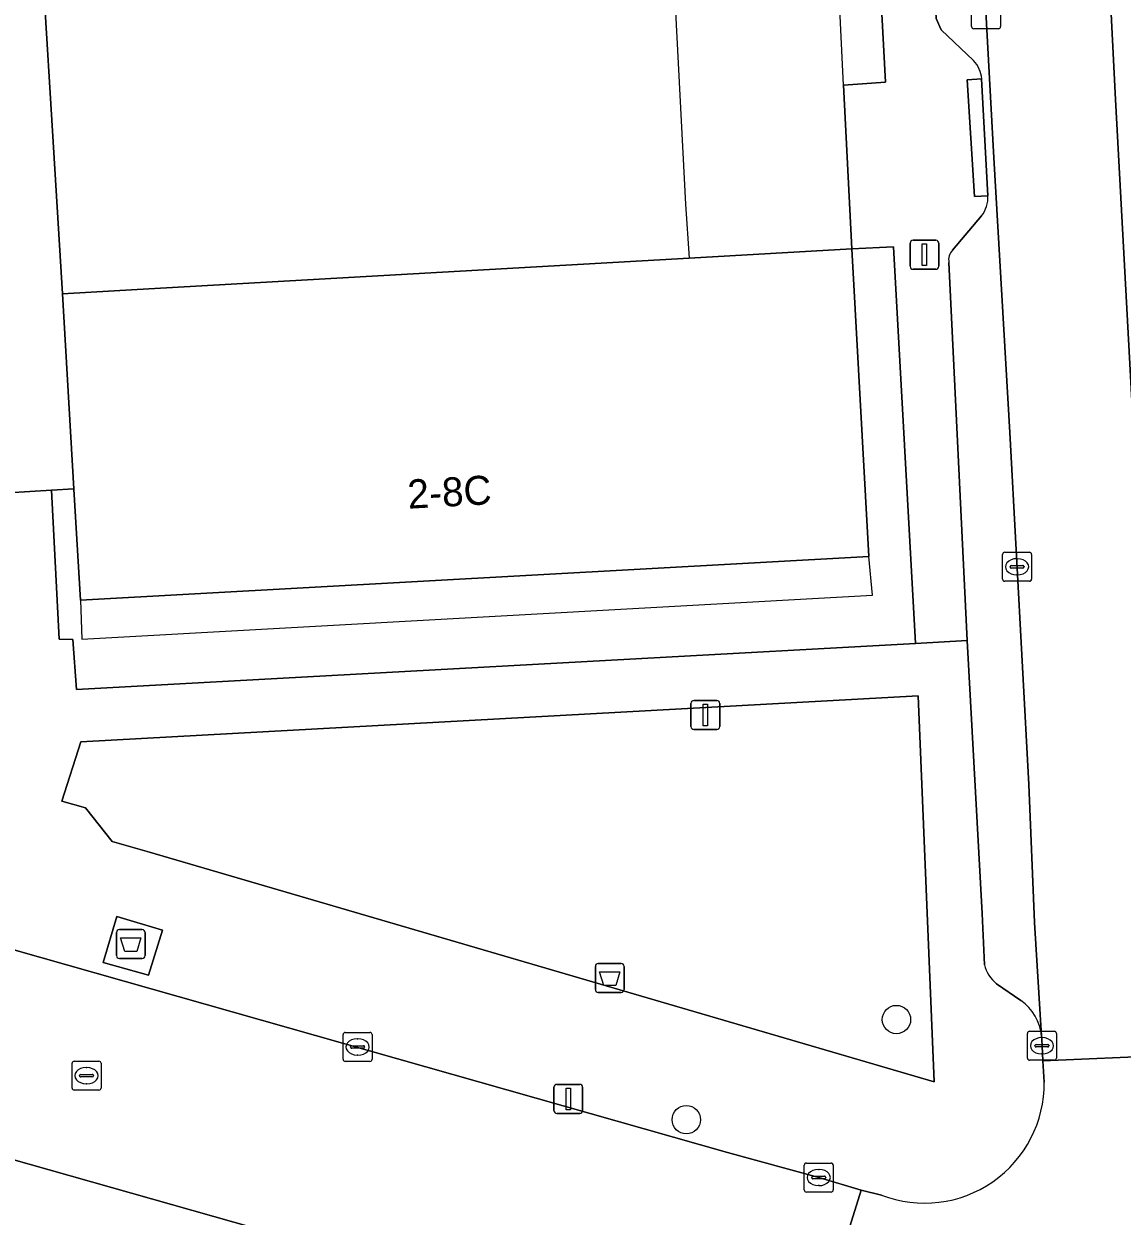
# Model space of a CAD drawing. Extents: x 158086 to 159499, y 382904 to 383981.
# Drawn here: x 158859.59 to 158897.48, y 383363.6 to 383404.74 of the extents above; entities that cross this region are included whole.
import ezdxf

# ---------------------------------------------------------------- set-up
doc = ezdxf.new("R2010")
doc.units = 0
for name, color, linetype in [('IMGEO_Afval_apart_plaats', 7, 'Continuous'), ('IMGEO_Afvalbak', 7, 'Continuous'), ('IMGEO_Boom', 7, 'Continuous'), ('IMGEO_Erf', 7, 'Continuous'), ('IMGEO_Groenvoorziening', 7, 'Continuous'), ('IMGEO_Kolk', 7, 'Continuous'), ('IMGEO_Lichtmast', 7, 'Continuous'), ('IMGEO_Pand', 7, 'Continuous'), ('IMGEO_Pand_nummerreeks', 7, 'Continuous'), ('IMGEO_Pand_overbouw', 7, 'Continuous'), ('IMGEO_Parkeervlak_open', 7, 'Continuous'), ('IMGEO_Rijbaan_lokaal_open', 7, 'Continuous'), ('IMGEO_Rioolput', 7, 'Continuous'), ('IMGEO_Voetpad_gesloten', 7, 'Continuous'), ('IMGEO_Voetpad_open', 7, 'Continuous')]:
    doc.layers.add(name, color=color, linetype=linetype)

msp = doc.modelspace()

# ---------------------------------------------------------------- linework, layer by layer
at = {"layer": 'IMGEO_Afval_apart_plaats'}
for p, q in [((158862.787, 383372.589), (158862.787, 383373.389)), ((158862.787, 383373.389), (158862.787, 383372.589)), ((158862.887, 383373.489), (158863.677, 383373.489)), ((158863.677, 383373.489), (158862.887, 383373.489)), ((158863.777, 383373.389), (158863.777, 383372.589)), ((158863.777, 383372.589), (158863.777, 383373.389)), ((158863.677, 383372.489), (158862.887, 383372.489)), ((158862.887, 383372.489), (158863.677, 383372.489))]:
    msp.add_line(p, q, dxfattribs=at)
msp.add_lwpolyline([(158862.93, 383373.203), (158863.634, 383373.203), (158863.485, 383372.733), (158863.079, 383372.733), (158862.93, 383373.203)], dxfattribs=at)
for centre, start, end in [((158862.887, 383373.389), 90, 180), ((158862.887, 383373.389), 90, 180), ((158863.677, 383373.389), 0, 90), ((158863.677, 383373.389), 360, 90), ((158862.887, 383372.589), 180, 270), ((158862.887, 383372.589), 180, 270), ((158863.677, 383372.589), 270, 0), ((158863.677, 383372.589), 270, 0)]:
    msp.add_arc(centre, 0.1, start, end, dxfattribs=at)
at = {"layer": 'IMGEO_Afvalbak'}
for p, q in [((158879.409, 383372.32), (158880.199, 383372.32)), ((158880.199, 383372.32), (158879.409, 383372.32)), ((158879.309, 383371.42), (158879.309, 383372.22)), ((158879.309, 383372.22), (158879.309, 383371.42)), ((158880.299, 383372.22), (158880.299, 383371.42)), ((158880.299, 383371.42), (158880.299, 383372.22)), ((158880.199, 383371.32), (158879.409, 383371.32)), ((158879.409, 383371.32), (158880.199, 383371.32))]:
    msp.add_line(p, q, dxfattribs=at)
msp.add_lwpolyline([(158879.452, 383372.034), (158880.156, 383372.034), (158880.007, 383371.564), (158879.601, 383371.564), (158879.452, 383372.034)], dxfattribs=at)
for centre, start, end in [((158879.409, 383372.22), 90, 180), ((158879.409, 383372.22), 90, 180), ((158880.199, 383372.22), 0, 90), ((158880.199, 383372.22), 360, 90), ((158879.409, 383371.42), 180, 270), ((158879.409, 383371.42), 180, 270), ((158880.199, 383371.42), 270, 0), ((158880.199, 383371.42), 270, 0)]:
    msp.add_arc(centre, 0.1, start, end, dxfattribs=at)
at = {"layer": 'IMGEO_Boom'}
for centre in [(158889.692, 383370.385), (158882.443, 383366.93)]:
    msp.add_circle(centre, 0.489, dxfattribs=at)
at = {"layer": 'IMGEO_Erf'}
msp.add_lwpolyline([(158859.946, 383411.358), (158860.921, 383395.428), (158863.497, 383395.575), (158882.537, 383396.66), (158888.148, 383396.98), (158887.866, 383402.627), (158889.313, 383402.728), (158888.966, 383409.167)], dxfattribs=at)
msp.add_lwpolyline([(158890.346, 383383.361), (158889.59, 383397.045), (158888.148, 383396.98), (158888.74, 383386.366), (158861.542, 383384.857), (158861.316, 383388.689), (158861.316, 383388.691), (158860.548, 383388.646), (158860.807, 383383.514), (158861.288, 383383.497), (158861.415, 383381.776)], close=True, dxfattribs=at)
at = {"layer": 'IMGEO_Groenvoorziening'}
msp.add_lwpolyline([(158890.994, 383368.232), (158890.436, 383381.549), (158861.562, 383379.967), (158860.904, 383377.92), (158861.717, 383377.691), (158862.644, 383376.53), (158863.927, 383376.159)], close=True, dxfattribs=at)
at = {"layer": 'IMGEO_Kolk'}
for p, q in [((158892.281, 383404.647), (158892.281, 383405.499)), ((158893.282, 383405.499), (158893.282, 383404.647)), ((158893.208, 383404.573), (158892.356, 383404.573)), ((158893.352, 383385.58), (158893.352, 383386.432)), ((158893.427, 383386.506), (158894.279, 383386.506)), ((158893.84, 383386.286), (158893.865, 383386.286)), ((158894.353, 383386.432), (158894.353, 383385.58)), ((158893.611, 383386), (158893.611, 383386.012)), ((158894.049, 383385.963), (158893.651, 383385.963)), ((158893.654, 383386.049), (158894.052, 383386.049)), ((158894.095, 383386.012), (158894.095, 383386)), ((158894.279, 383385.506), (158893.427, 383385.506)), ((158893.863, 383385.726), (158893.838, 383385.726)), ((158870.604, 383369.013), (158870.604, 383369.865)), ((158870.679, 383369.939), (158871.531, 383369.939)), ((158871.605, 383369.865), (158871.605, 383369.013)), ((158894.211, 383369.055), (158894.211, 383369.907)), ((158894.286, 383369.981), (158895.138, 383369.981)), ((158895.212, 383369.907), (158895.212, 383369.055)), ((158870.863, 383369.433), (158870.863, 383369.445)), ((158870.906, 383369.482), (158871.304, 383369.482)), ((158871.092, 383369.719), (158871.117, 383369.719)), ((158871.347, 383369.445), (158871.347, 383369.433)), ((158894.47, 383369.475), (158894.47, 383369.487)), ((158894.908, 383369.438), (158894.51, 383369.438)), ((158894.513, 383369.524), (158894.911, 383369.524)), ((158894.699, 383369.761), (158894.724, 383369.761)), ((158894.954, 383369.487), (158894.954, 383369.475)), ((158871.301, 383369.396), (158870.903, 383369.396)), ((158871.115, 383369.159), (158871.09, 383369.159)), ((158894.722, 383369.201), (158894.697, 383369.201)), ((158871.531, 383368.939), (158870.679, 383368.939)), ((158895.138, 383368.981), (158894.286, 383368.981)), ((158886.51, 383364.508), (158886.51, 383365.36)), ((158886.585, 383365.434), (158887.437, 383365.434)), ((158887.511, 383365.36), (158887.511, 383364.508)), ((158886.769, 383364.928), (158886.769, 383364.94)), ((158887.207, 383364.891), (158886.809, 383364.891)), ((158886.812, 383364.977), (158887.21, 383364.977)), ((158886.998, 383365.214), (158887.023, 383365.214)), ((158887.253, 383364.94), (158887.253, 383364.928)), ((158887.021, 383364.654), (158886.996, 383364.654)), ((158887.437, 383364.434), (158886.585, 383364.434))]:
    msp.add_line(p, q, dxfattribs=at)
for points in [[(158892.281, 383404.647), (158892.281, 383405.499)], [(158893.282, 383405.499), (158893.282, 383404.647)], [(158893.208, 383404.573), (158892.356, 383404.573)], [(158893.352, 383385.58), (158893.352, 383386.432)], [(158893.427, 383386.506), (158894.279, 383386.506)], [(158894.353, 383386.432), (158894.353, 383385.58)], [(158894.279, 383385.506), (158893.427, 383385.506)], [(158870.604, 383369.013), (158870.604, 383369.865)], [(158870.679, 383369.939), (158871.531, 383369.939)], [(158871.605, 383369.865), (158871.605, 383369.013)], [(158894.211, 383369.055), (158894.211, 383369.907)], [(158894.286, 383369.981), (158895.138, 383369.981)], [(158895.212, 383369.907), (158895.212, 383369.055)], [(158871.531, 383368.939), (158870.679, 383368.939)], [(158895.138, 383368.981), (158894.286, 383368.981)], [(158886.51, 383364.508), (158886.51, 383365.36)], [(158886.585, 383365.434), (158887.437, 383365.434)], [(158887.511, 383365.36), (158887.511, 383364.508)], [(158887.437, 383364.434), (158886.585, 383364.434)]]:
    msp.add_lwpolyline(points, dxfattribs=at)
for centre, radius, start, end in [((158892.358, 383404.649), 0.0765, 181.552, 268.448), ((158892.358, 383404.649), 0.0765, 181.552, 268.448), ((158893.206, 383404.649), 0.0765, 271.552, 358.448), ((158893.206, 383404.649), 0.0765, 271.552, 358.448), ((158893.429, 383386.43), 0.0765, 91.552, 178.448), ((158893.429, 383386.43), 0.0765, 91.552, 178.448), ((158894.277, 383386.43), 0.0765, 1.552, 88.448), ((158894.277, 383386.43), 0.0765, 1.552, 88.448), ((158893.651, 383386.009), 0.0403, 85.8775, 175.7526), ((158893.648, 383385.999), 0.0366, 178.938, 274.7102), ((158894.052, 383386.006), 0.043, 264.8664, 352.4533), ((158894.056, 383386.011), 0.0386, 1.7309, 96.639), ((158893.429, 383385.582), 0.0765, 181.552, 268.448), ((158893.429, 383385.582), 0.0765, 181.552, 268.448), ((158894.277, 383385.582), 0.0765, 271.552, 358.448), ((158894.277, 383385.582), 0.0765, 271.552, 358.448), ((158870.681, 383369.863), 0.0765, 91.552, 178.448), ((158870.681, 383369.863), 0.0765, 91.552, 178.448), ((158871.529, 383369.863), 0.0765, 1.552, 88.448), ((158871.529, 383369.863), 0.0765, 1.552, 88.448), ((158894.288, 383369.905), 0.0765, 91.552, 178.448), ((158894.288, 383369.905), 0.0765, 91.552, 178.448), ((158895.136, 383369.905), 0.0765, 1.552, 88.448), ((158895.136, 383369.905), 0.0765, 1.552, 88.448), ((158870.903, 383369.442), 0.0403, 85.8775, 175.7526), ((158870.9, 383369.432), 0.0366, 178.938, 274.7102), ((158871.304, 383369.439), 0.043, 264.8664, 352.4533), ((158871.308, 383369.444), 0.0386, 1.7309, 96.639), ((158894.51, 383369.484), 0.0403, 85.8775, 175.7526), ((158894.507, 383369.474), 0.0366, 178.938, 274.7102), ((158894.911, 383369.481), 0.043, 264.8664, 352.4533), ((158894.915, 383369.486), 0.0386, 1.7309, 96.639), ((158870.681, 383369.015), 0.0765, 181.552, 268.448), ((158870.681, 383369.015), 0.0765, 181.552, 268.448), ((158871.529, 383369.015), 0.0765, 271.552, 358.448), ((158871.529, 383369.015), 0.0765, 271.552, 358.448), ((158894.288, 383369.057), 0.0765, 181.552, 268.448), ((158894.288, 383369.057), 0.0765, 181.552, 268.448), ((158895.136, 383369.057), 0.0765, 271.552, 358.448), ((158895.136, 383369.057), 0.0765, 271.552, 358.448), ((158886.587, 383365.358), 0.0765, 91.552, 178.448), ((158886.587, 383365.358), 0.0765, 91.552, 178.448), ((158887.435, 383365.358), 0.0765, 1.552, 88.448), ((158887.435, 383365.358), 0.0765, 1.552, 88.448), ((158886.809, 383364.937), 0.0403, 85.8775, 175.7526), ((158886.806, 383364.927), 0.0366, 178.938, 274.7102), ((158887.21, 383364.934), 0.043, 264.8664, 352.4533), ((158887.214, 383364.939), 0.0386, 1.7309, 96.639), ((158886.587, 383364.51), 0.0765, 181.552, 268.448), ((158886.587, 383364.51), 0.0765, 181.552, 268.448), ((158887.435, 383364.51), 0.0765, 271.552, 358.448), ((158887.435, 383364.51), 0.0765, 271.552, 358.448)]:
    msp.add_arc(centre, radius, start, end, dxfattribs=at)
for centre, major_axis, ratio, start_param, end_param in [((158893.839, 383386.006), (-0.387, 0.002), 0.722429, 4.712389, 7.853982), ((158893.864, 383386.006), (-0.39, 0.002), 0.717154, 1.570796, 4.712389), ((158871.091, 383369.439), (-0.387, 0.002), 0.722429, 4.712389, 7.853982), ((158871.116, 383369.439), (-0.39, 0.002), 0.717154, 1.570796, 4.712389), ((158894.698, 383369.481), (-0.387, 0.002), 0.722429, 4.712389, 7.853982), ((158894.723, 383369.481), (-0.39, 0.002), 0.717154, 1.570796, 4.712389), ((158886.997, 383364.934), (-0.387, 0.002), 0.722429, 4.712389, 7.853982), ((158887.022, 383364.934), (-0.39, 0.002), 0.717154, 1.570796, 4.712389)]:
    msp.add_ellipse(centre, major_axis=major_axis, ratio=ratio, start_param=start_param, end_param=end_param, dxfattribs=at)
at = {"layer": 'IMGEO_Lichtmast'}
for p, q in [((158890.164, 383396.374), (158890.164, 383397.174)), ((158890.164, 383397.174), (158890.164, 383396.374)), ((158890.264, 383397.274), (158891.054, 383397.274)), ((158891.054, 383397.274), (158890.264, 383397.274)), ((158891.154, 383397.174), (158891.154, 383396.374)), ((158891.154, 383396.374), (158891.154, 383397.174)), ((158891.054, 383396.274), (158890.264, 383396.274)), ((158890.264, 383396.274), (158891.054, 383396.274)), ((158882.705, 383381.394), (158883.495, 383381.394)), ((158883.495, 383381.394), (158882.705, 383381.394)), ((158882.605, 383380.494), (158882.605, 383381.294)), ((158882.605, 383381.294), (158882.605, 383380.494)), ((158883.595, 383381.294), (158883.595, 383380.494)), ((158883.595, 383380.494), (158883.595, 383381.294)), ((158883.495, 383380.394), (158882.705, 383380.394)), ((158882.705, 383380.394), (158883.495, 383380.394)), ((158877.876, 383367.246), (158877.876, 383368.046)), ((158877.876, 383368.046), (158877.876, 383367.246)), ((158877.976, 383368.146), (158878.766, 383368.146)), ((158878.766, 383368.146), (158877.976, 383368.146)), ((158878.866, 383368.046), (158878.866, 383367.246)), ((158878.866, 383367.246), (158878.866, 383368.046)), ((158878.766, 383367.146), (158877.976, 383367.146)), ((158877.976, 383367.146), (158878.766, 383367.146))]:
    msp.add_line(p, q, dxfattribs=at)
for points in [[(158890.584, 383397.149), (158890.734, 383397.149), (158890.734, 383396.399), (158890.584, 383396.399), (158890.584, 383397.149)], [(158883.025, 383381.269), (158883.175, 383381.269), (158883.175, 383380.519), (158883.025, 383380.519), (158883.025, 383381.269)], [(158878.296, 383368.021), (158878.446, 383368.021), (158878.446, 383367.271), (158878.296, 383367.271), (158878.296, 383368.021)]]:
    msp.add_lwpolyline(points, dxfattribs=at)
for centre, start, end in [((158890.264, 383397.174), 90, 180), ((158890.264, 383397.174), 90, 180), ((158891.054, 383397.174), 0, 90), ((158891.054, 383397.174), 360, 90), ((158890.264, 383396.374), 180, 270), ((158890.264, 383396.374), 180, 270), ((158891.054, 383396.374), 270, 0), ((158891.054, 383396.374), 270, 0), ((158882.705, 383381.294), 90, 180), ((158882.705, 383381.294), 90, 180), ((158883.495, 383381.294), 0, 90), ((158883.495, 383381.294), 360, 90), ((158882.705, 383380.494), 180, 270), ((158882.705, 383380.494), 180, 270), ((158883.495, 383380.494), 270, 0), ((158883.495, 383380.494), 270, 0), ((158877.976, 383368.046), 90, 180), ((158877.976, 383368.046), 90, 180), ((158878.766, 383368.046), 0, 90), ((158878.766, 383368.046), 360, 90), ((158877.976, 383367.246), 180, 270), ((158877.976, 383367.246), 180, 270), ((158878.766, 383367.246), 270, 0), ((158878.766, 383367.246), 270, 0)]:
    msp.add_arc(centre, 0.1, start, end, dxfattribs=at)
at = {"layer": 'IMGEO_Pand'}
msp.add_lwpolyline([(158888.148, 383396.98), (158882.537, 383396.66), (158863.497, 383395.575), (158860.921, 383395.428), (158861.316, 383388.691), (158861.316, 383388.689), (158861.542, 383384.857), (158888.74, 383386.366)], close=True, dxfattribs=at)
at = {"layer": 'IMGEO_Pand_overbouw'}
for points in [[(158888.148, 383396.98), (158887.866, 383402.627), (158887.724, 383405.488), (158882.071, 383405.154), (158882.42, 383398.523), (158882.537, 383396.66)], [(158888.74, 383386.366), (158861.542, 383384.857), (158861.589, 383383.507), (158888.87, 383385.025)]]:
    msp.add_lwpolyline(points, close=True, dxfattribs=at)
at = {"layer": 'IMGEO_Parkeervlak_open'}
for points in [[(158895.987, 383427.119), (158896.019, 383426.484), (158897.244, 383402.134), (158898.446, 383380.066)], [(158894.699, 383369.809), (158894.456, 383373.735), (158894.26, 383378.492), (158893.604, 383390.635), (158893.053, 383400.112), (158891.628, 383426.244)], [(158889.895, 383424.071), (158890.489, 383415.514), (158891.06, 383404.924), (158891.232, 383404.53), (158892.354, 383403.472)], [(158892.631, 383402.843), (158892.849, 383398.806)], [(158892.631, 383398.111), (158891.63, 383396.93)], [(158891.503, 383396.509), (158892.132, 383383.459), (158892.651, 383374.041), (158892.729, 383372.275)], [(158893.146, 383371.618), (158893.981, 383371.042)]]:
    msp.add_lwpolyline(points, dxfattribs=at)
for centre, radius, start, end in [((158891.63, 383402.777), 1.004, 3.7442, 43.7914), ((158891.746, 383398.77), 1.103, 323.3135, 1.8564), ((158891.923, 383396.612), 0.432, 132.6355, 193.7913), ((158893.901, 383372.558), 1.206, 193.5777, 231.2292), ((158892.999, 383369.645), 1.708, 5.5187, 54.9075)]:
    msp.add_arc(centre, radius, start, end, dxfattribs=at)
at = {"layer": 'IMGEO_Rijbaan_lokaal_open'}
for points in [[(158894.456, 383373.735), (158894.699, 383369.809), (158894.706, 383369.689), (158894.713, 383369.482), (158894.744, 383368.957), (158899.011, 383369.142), (158899.005, 383369.252), (158898.835, 383372.537), (158898.642, 383376.28), (158898.446, 383380.066), (158897.244, 383402.134), (158896.019, 383426.484), (158891.628, 383426.244), (158893.053, 383400.112), (158893.604, 383390.635), (158894.26, 383378.492)], [(158886.403, 383357.857), (158888.47, 383364.499), (158887.011, 383364.933), (158883.863, 383365.795), (158850.696, 383375.212), (158839.319, 383378.442), (158832.46, 383380.397), (158830.515, 383373.709), (158830.616, 383373.672), (158836.657, 383371.953), (158848.856, 383368.492), (158851.376, 383367.777), (158854.716, 383366.83), (158855.909, 383366.491), (158859.089, 383365.589), (158880.188, 383359.604), (158886.223, 383357.899)]]:
    msp.add_lwpolyline(points, close=True, dxfattribs=at)
for points in [[(158899.156, 383366.41), (158899.011, 383369.142), (158894.744, 383368.957), (158894.787, 383368.227)], [(158889.178, 383364.324), (158888.47, 383364.499), (158886.403, 383357.857), (158895.754, 383355.173), (158898.685, 383354.576)]]:
    msp.add_lwpolyline(points, dxfattribs=at)
msp.add_arc((158890.659, 383368.178), 4.128, 248.9793, 0.6847, dxfattribs=at)
at = {"layer": 'IMGEO_Rioolput'}
for p, q in [((158861.255, 383368.022), (158861.255, 383368.874)), ((158861.33, 383368.948), (158862.182, 383368.948)), ((158861.743, 383368.728), (158861.768, 383368.728)), ((158862.256, 383368.874), (158862.256, 383368.022)), ((158861.514, 383368.442), (158861.514, 383368.454)), ((158861.952, 383368.405), (158861.554, 383368.405)), ((158861.557, 383368.491), (158861.955, 383368.491)), ((158861.998, 383368.454), (158861.998, 383368.442)), ((158862.182, 383367.948), (158861.33, 383367.948)), ((158861.766, 383368.168), (158861.741, 383368.168))]:
    msp.add_line(p, q, dxfattribs=at)
for points in [[(158861.255, 383368.022), (158861.255, 383368.874)], [(158861.33, 383368.948), (158862.182, 383368.948)], [(158862.256, 383368.874), (158862.256, 383368.022)], [(158862.182, 383367.948), (158861.33, 383367.948)]]:
    msp.add_lwpolyline(points, dxfattribs=at)
for centre, radius, start, end in [((158861.332, 383368.872), 0.0765, 91.552, 178.448), ((158861.332, 383368.872), 0.0765, 91.552, 178.448), ((158862.18, 383368.872), 0.0765, 1.552, 88.448), ((158862.18, 383368.872), 0.0765, 1.552, 88.448), ((158861.554, 383368.451), 0.0403, 85.8775, 175.7526), ((158861.551, 383368.441), 0.0366, 178.938, 274.7102), ((158861.955, 383368.448), 0.043, 264.8664, 352.4533), ((158861.959, 383368.453), 0.0386, 1.7309, 96.639), ((158861.332, 383368.024), 0.0765, 181.552, 268.448), ((158861.332, 383368.024), 0.0765, 181.552, 268.448), ((158862.18, 383368.024), 0.0765, 271.552, 358.448), ((158862.18, 383368.024), 0.0765, 271.552, 358.448)]:
    msp.add_arc(centre, radius, start, end, dxfattribs=at)
for centre, major_axis, ratio, start_param, end_param in [((158861.742, 383368.448), (-0.387, 0.002), 0.722429, 4.712389, 7.853982), ((158861.767, 383368.448), (-0.39, 0.002), 0.717154, 1.570796, 4.712389)]:
    msp.add_ellipse(centre, major_axis=major_axis, ratio=ratio, start_param=start_param, end_param=end_param, dxfattribs=at)
at = {"layer": 'IMGEO_Voetpad_gesloten'}
msp.add_lwpolyline([(158862.325, 383372.355), (158863.897, 383371.911), (158864.377, 383373.474), (158862.805, 383373.936)], close=True, dxfattribs=at)
at = {"layer": 'IMGEO_Voetpad_open'}
for points in [[(158892.354, 383403.472), (158891.232, 383404.53), (158891.06, 383404.924), (158890.489, 383415.514), (158889.895, 383424.071)], [(158858.015, 383408.036), (158858.195, 383404.667), (158858.321, 383402.304), (158858.001, 383402.287), (158858.178, 383398.968), (158858.47, 383398.984), (158858.596, 383396.621), (158859.052, 383388.561), (158860.548, 383388.646), (158861.316, 383388.691), (158860.921, 383395.428), (158859.946, 383411.358)], [(158888.966, 383409.167), (158889.313, 383402.728), (158887.866, 383402.627), (158888.148, 383396.98), (158889.59, 383397.045), (158890.346, 383383.361), (158892.132, 383383.459), (158891.503, 383396.509)], [(158892.849, 383398.806), (158892.383, 383398.783), (158892.135, 383402.804), (158892.631, 383402.843)], [(158891.63, 383396.93), (158892.631, 383398.111)], [(158898.685, 383354.576), (158895.754, 383355.173), (158886.403, 383357.857), (158886.223, 383357.899), (158880.188, 383359.604), (158859.089, 383365.589), (158858.805, 383364.588), (158855.625, 383365.49), (158855.909, 383366.491), (158854.716, 383366.83), (158854.432, 383365.829), (158851.092, 383366.776), (158851.376, 383367.777), (158848.856, 383368.492), (158836.657, 383371.953), (158830.616, 383373.672), (158830.515, 383373.709), (158811.299, 383379.137), (158810.816, 383379.277), (158803.832, 383381.26), (158764.081, 383392.596), (158757.401, 383394.452), (158756.229, 383394.782), (158753.608, 383395.531)], [(158892.729, 383372.275), (158892.651, 383374.041), (158892.132, 383383.459), (158890.346, 383383.361), (158861.415, 383381.776), (158861.288, 383383.497), (158860.807, 383383.514), (158860.548, 383388.646), (158859.052, 383388.561), (158859.06, 383388.389), (158858.913, 383388.382), (158859.215, 383382.413), (158851.866, 383379.487), (158847.018, 383380.843), (158834.956, 383384.215), (158829.944, 383385.617), (158827.43, 383385.987)], [(158830.654, 383380.927), (158832.46, 383380.397), (158839.319, 383378.442), (158850.696, 383375.212), (158883.863, 383365.795), (158887.011, 383364.933), (158888.47, 383364.499), (158889.178, 383364.324)], [(158893.981, 383371.042), (158893.146, 383371.618)], [(158894.787, 383368.227), (158894.744, 383368.957), (158894.713, 383369.482), (158894.706, 383369.689), (158894.699, 383369.809)]]:
    msp.add_lwpolyline(points, dxfattribs=at)
for points in [[(158892.849, 383398.806), (158892.631, 383402.843), (158892.135, 383402.804), (158892.383, 383398.783)], [(158890.994, 383368.232), (158863.927, 383376.159), (158862.644, 383376.53), (158861.717, 383377.691), (158860.904, 383377.92), (158861.562, 383379.967), (158890.436, 383381.549)], [(158863.897, 383371.911), (158862.325, 383372.355), (158862.805, 383373.936), (158864.377, 383373.474)]]:
    msp.add_lwpolyline(points, close=True, dxfattribs=at)
for centre, radius, start, end in [((158891.63, 383402.777), 1.004, 3.7442, 43.7914), ((158891.746, 383398.77), 1.103, 323.3135, 1.8564), ((158891.923, 383396.612), 0.432, 132.6355, 193.7913), ((158893.901, 383372.558), 1.206, 193.5777, 231.2292), ((158892.999, 383369.645), 1.708, 5.5187, 54.9075), ((158890.659, 383368.178), 4.128, 248.9793, 0.6847)]:
    msp.add_arc(centre, radius, start, end, dxfattribs=at)

# ---------------------------------------------------------------- texts
at = {"layer": 'IMGEO_Pand_nummerreeks'}
msp.add_text('2-8C', height=1, rotation=3.1742, dxfattribs=at).set_placement((158872.854, 383388.009))

doc.saveas('drawing.dxf')
